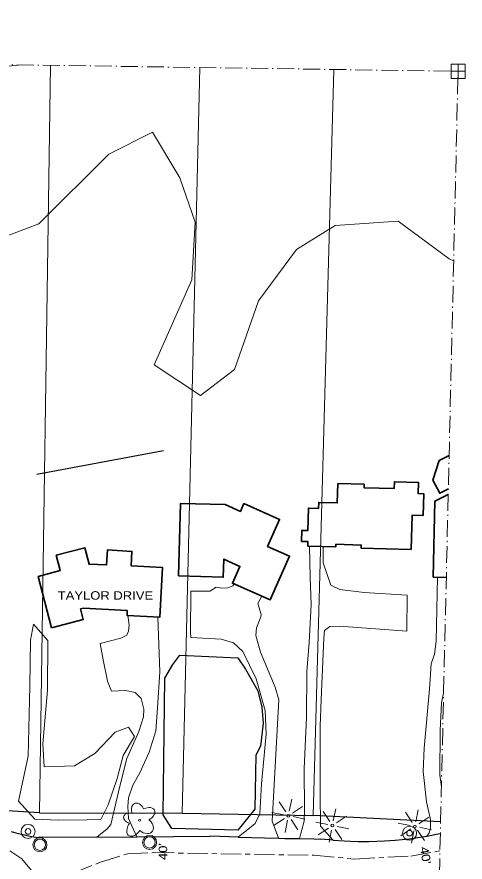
# Model space of a CAD drawing. Extents: x -861682 to -858969, y -1797841 to -1795153.
# Drawn here: x -859288 to -858969, y -1795757 to -1795158 of the extents above; entities that cross this region are included whole.
import ezdxf

# ---------------------------------------------------------------- set-up
doc = ezdxf.new("R2010")
doc.units = 0
doc.header["$LTSCALE"] = 2.4
doc.linetypes.add('DOT_DASHED', pattern=[7.7, 5, -1.2, 0.3, -1.2])
doc.linetypes.add('LONG_DASH_SHORT_DASH', pattern=[9.9, 6, -1.2, 1.5, -1.2])
for name, color, linetype, lineweight in [('10', 7, 'Continuous', 25), ('11', 7, 'Continuous', 13), ('12', 7, 'Continuous', 35), ('14', 7, 'Continuous', 25), ('17', 7, 'Continuous', 13), ('18', 7, 'Continuous', 13), ('30', 7, 'Continuous', 13), ('31', 7, 'Continuous', 13), ('32', 7, 'LONG_DASH_SHORT_DASH', 13), ('36', 7, 'Continuous', 13), ('42', 7, 'Continuous', 25), ('46', 7, 'Continuous', 13), ('61', 7, 'Continuous', 13)]:
    doc.layers.add(name, color=color, linetype=linetype, lineweight=lineweight)
doc.layers.add('43', color=7, linetype='Continuous')

msp = doc.modelspace()

# ---------------------------------------------------------------- linework, layer by layer
at = {"layer": '10'}
for p, q in [((-859230.781, -1795739.45), (-859272.109, -1795739.71)), ((-859130.522, -1795739.561), (-859150.348, -1795738.944)), ((-859062.976, -1795741.728), (-859071.75, -1795740.863))]:
    msp.add_line(p, q, dxfattribs=at)
for points in [[(-859291.594, -1795735.461), (-859288.291, -1795736.524), (-859277.069, -1795739.077), (-859272.109, -1795739.71)], [(-859230.781, -1795739.45), (-859202.511, -1795739.272), (-859150.348, -1795738.944)], [(-859130.522, -1795739.561), (-859111.795, -1795740.062), (-859101.943, -1795740.288)], [(-859101.943, -1795740.288), (-859097.473, -1795740.391), (-859086.862, -1795740.591)], [(-859086.862, -1795740.591), (-859076.749, -1795740.783), (-859071.75, -1795740.863)], [(-859062.976, -1795741.728), (-859055.28, -1795742.244), (-859050.876, -1795742.439), (-859045.368, -1795742.579), (-859043.164, -1795742.603), (-859040.96, -1795742.609), (-859037.654, -1795742.583), (-859032.146, -1795742.448), (-859026.642, -1795742.199), (-859018.947, -1795741.658), (-859009.083, -1795740.634), (-858998.176, -1795739.064), (-858996.617, -1795738.776)], [(-858996.617, -1795738.776), (-858988.463, -1795737.272), (-858987.024, -1795736.964)]]:
    msp.add_lwpolyline(points, dxfattribs=at)
at = {"layer": '11'}
for points in [[(-859079.865, -1795533.007), (-859079.451, -1795555.209), (-859078.572, -1795574.443), (-859080.099, -1795601.413), (-859081.687, -1795622.019), (-859082.041, -1795654.325), (-859083.692, -1795690.95), (-859083.301, -1795720.031), (-859083.759, -1795728.122), (-859086.862, -1795740.591)], [(-859070.103, -1795533.269), (-859070.088, -1795544.987), (-859064.66, -1795560.825), (-859058.323, -1795563.713), (-859041.158, -1795565.88), (-859010.659, -1795567.747), (-859010.846, -1795593.387), (-859058.541, -1795589.913), (-859065.539, -1795590.009), (-859069.327, -1795592.992), (-859069.732, -1795598.275), (-859071.632, -1795641.773), (-859072.292, -1795660.886), (-859072.28, -1795708.462), (-859071.978, -1795731.67), (-859062.976, -1795741.728)], [(-858989.081, -1795555.168), (-858989.922, -1795600.415), (-858991.154, -1795609.763), (-858993.574, -1795616.512), (-858994.731, -1795634.472), (-858998.44, -1795676.392), (-858999.092, -1795692.87), (-858996.795, -1795714.364), (-858994.07, -1795727.062), (-858993.989, -1795733.075), (-858994.954, -1795736.464), (-858996.617, -1795738.776)], [(-859133.293, -1795559.908), (-859134.27, -1795561.133), (-859137.867, -1795562.616), (-859142.409, -1795562.781), (-859146.059, -1795562.082), (-859150.585, -1795565.058), (-859164.004, -1795565.001), (-859164.381, -1795594.004), (-859164.035, -1795597.818), (-859142.455, -1795598.969), (-859133.711, -1795601.538), (-859127.175, -1795607.74), (-859117.627, -1795627.15), (-859111.239, -1795649.613), (-859110.644, -1795666.407), (-859113.912, -1795701.781), (-859115.187, -1795723.073), (-859118.522, -1795729.841), (-859130.522, -1795739.561)], [(-859113.738, -1795568.59), (-859116.608, -1795573.764), (-859114.269, -1795581.486), (-859114.364, -1795583.167), (-859117.552, -1795591.068), (-859117.924, -1795596.388), (-859114.657, -1795608.203), (-859104.327, -1795633.033), (-859101.534, -1795642.046), (-859106.338, -1795728.141), (-859101.943, -1795740.288)], [(-859208.745, -1795582.207), (-859207.806, -1795588.945), (-859208.266, -1795593.346), (-859209.619, -1795596.151), (-859213.681, -1795598.381), (-859228.443, -1795602.183), (-859226.423, -1795613.682), (-859223.211, -1795628.938), (-859220.375, -1795635.95), (-859210.435, -1795635.388), (-859203.629, -1795636.828), (-859199.44, -1795641.035), (-859197.446, -1795648.633), (-859197.722, -1795654.134), (-859201.059, -1795664.662), (-859209.517, -1795683.719), (-859214.562, -1795703.321), (-859220.95, -1795730.507), (-859223.44, -1795733.529), (-859230.781, -1795739.45)], [(-859187.392, -1795583.462), (-859186.147, -1795622.216), (-859187.665, -1795647.781), (-859189.009, -1795664.079), (-859193.773, -1795679.34), (-859200.259, -1795693.976), (-859205.252, -1795702.724), (-859208.215, -1795711.622), (-859208.846, -1795717.805), (-859208.348, -1795726.372), (-859202.511, -1795739.272)], [(-858984.702, -1795637.258), (-858986.213, -1795644.126), (-858987.117, -1795663.822), (-858987.434, -1795695.498), (-858986.252, -1795703.832)]]:
    msp.add_lwpolyline(points, dxfattribs=at)
at = {"layer": '12'}
msp.add_line((-858982.794, -1795555.319), (-858992.181, -1795555.094), dxfattribs=at)
for points in [[(-858981.327, -1795492.318), (-858987.472, -1795495.486), (-858992.217, -1795486.281), (-858987.848, -1795472.344), (-858980.777, -1795468.699)], [(-858992.181, -1795555.094), (-858990.883, -1795501.126), (-858981.421, -1795496.385)]]:
    msp.add_lwpolyline(points, dxfattribs=at)
for points in [[(-859007.647, -1795535.345), (-859043.222, -1795534.385), (-859043.164, -1795532.24), (-859061.136, -1795531.754), (-859061.183, -1795533.508), (-859081.111, -1795532.974), (-859081.028, -1795529.861), (-859085.542, -1795529.741), (-859085.333, -1795521.863), (-859081.052, -1795521.977), (-859080.628, -1795506.045), (-859073.408, -1795506.237), (-859073.296, -1795502.043), (-859060.114, -1795502.395), (-859059.748, -1795488.682), (-859041.117, -1795489.179), (-859041.182, -1795491.625), (-859019.778, -1795492.194), (-859019.65, -1795487.384), (-859002.594, -1795487.838), (-859002.803, -1795495.703), (-858998.779, -1795495.81), (-858999.191, -1795511.298), (-859007.002, -1795511.09)], [(-859172.795, -1795554.211), (-859171.355, -1795502.711), (-859139.606, -1795503.599), (-859128.918, -1795508.345), (-859126.468, -1795502.827), (-859101.107, -1795514.087), (-859109.591, -1795533.196), (-859094.042, -1795540.099), (-859107.851, -1795571.204), (-859134.518, -1795559.364), (-859129.214, -1795547.418), (-859140.687, -1795542.232), (-859141.047, -1795555.099)], [(-859263.001, -1795590.988), (-859272.459, -1795554.471), (-859256.757, -1795550.404), (-859259.592, -1795539.458), (-859239.305, -1795534.204), (-859236.281, -1795545.88), (-859223.885, -1795546.363), (-859223.261, -1795535.753), (-859205.939, -1795536.771), (-859206.538, -1795546.96), (-859184.118, -1795548.278), (-859186.204, -1795583.532), (-859209.382, -1795582.17), (-859209.183, -1795578.785), (-859240.312, -1795577.058), (-859242.426, -1795577.606), (-859240.471, -1795585.154)]]:
    msp.add_lwpolyline(points, close=True, dxfattribs=at)
at = {"layer": '14'}
msp.add_line((-859273.428, -1795481.906), (-859183.436, -1795465.071), dxfattribs=at)
for points in [[(-859182.593, -1795626.694), (-859176.951, -1795617.035), (-859172.007, -1795610.392), (-859130.65, -1795612.242), (-859125.27, -1795620.242), (-859116.619, -1795635.63), (-859113.696, -1795647.32), (-859112.691, -1795658.726)], [(-859112.691, -1795658.726), (-859114.555, -1795674.941), (-859117.944, -1795681.426), (-859118.708, -1795719.752), (-859130.656, -1795734.677), (-859177.459, -1795733.433), (-859183.731, -1795723.801), (-859182.593, -1795626.694)]]:
    msp.add_lwpolyline(points, dxfattribs=at)
at = {"layer": '17'}
for p, q in [((-859096.658, -1795721.504), (-859101.448, -1795714.376)), ((-859094.198, -1795721.044), (-859092.472, -1795712.644)), ((-859098.158, -1795723.704), (-859106.62, -1795722.03)), ((-859091.998, -1795722.444), (-859084.902, -1795717.704)), ((-859065.425, -1795728.402), (-859070.215, -1795721.274)), ((-859062.965, -1795727.942), (-859061.239, -1795719.542)), ((-859006.922, -1795729.044), (-859011.712, -1795721.916)), ((-859004.462, -1795728.584), (-859002.736, -1795720.184)), ((-859097.618, -1795726.204), (-859104.844, -1795731.06)), ((-859097.238, -1795736.164), (-859095.558, -1795727.564)), ((-859092.898, -1795727.104), (-859088.098, -1795734.318)), ((-859091.558, -1795724.964), (-859083.078, -1795726.688)), ((-859066.925, -1795730.602), (-859075.387, -1795728.928)), ((-859060.765, -1795729.342), (-859053.669, -1795724.602)), ((-859008.422, -1795731.244), (-859016.884, -1795729.57)), ((-859002.262, -1795729.984), (-858995.166, -1795725.244)), ((-859066.385, -1795733.102), (-859073.611, -1795737.958)), ((-859066.005, -1795743.062), (-859064.325, -1795734.462)), ((-859061.665, -1795734.002), (-859056.865, -1795741.216)), ((-859060.325, -1795731.862), (-859051.845, -1795733.586)), ((-859007.882, -1795733.744), (-859015.108, -1795738.6)), ((-859007.502, -1795743.704), (-859005.822, -1795735.104)), ((-859003.162, -1795734.644), (-858998.362, -1795741.858)), ((-859001.822, -1795732.504), (-858993.342, -1795734.228))]:
    msp.add_line(p, q, dxfattribs=at)
msp.add_lwpolyline([(-859200.252, -1795734.881), (-859199.21, -1795735.649), (-859197.804, -1795736.371), (-859196.556, -1795736.777), (-859195.184, -1795736.973), (-859194.166, -1795736.923), (-859193.022, -1795736.633), (-859192.09, -1795736.081), (-859191.35, -1795735.293), (-859190.882, -1795734.335), (-859190.672, -1795733.257), (-859190.776, -1795732.061), (-859191.066, -1795730.889), (-859191.552, -1795729.829), (-859192.274, -1795728.685), (-859193.14, -1795727.765), (-859193.822, -1795727.153), (-859192.64, -1795726.437), (-859191.494, -1795725.489), (-859190.574, -1795724.397), (-859190.052, -1795723.541), (-859189.72, -1795722.727), (-859189.574, -1795721.911), (-859189.614, -1795721.149), (-859189.83, -1795720.469), (-859190.088, -1795720.017), (-859190.508, -1795719.543), (-859190.968, -1795719.189), (-859191.534, -1795718.899), (-859192.77, -1795718.571), (-859194.012, -1795718.537), (-859196.058, -1795718.913), (-859197.718, -1795719.551), (-859198.508, -1795717.973), (-859199.162, -1795717.159), (-859199.574, -1795716.757), (-859200.038, -1795716.357), (-859200.64, -1795715.965), (-859201.644, -1795715.533), (-859202.658, -1795715.363), (-859203.546, -1795715.463), (-859204.346, -1795715.797), (-859205.012, -1795716.283), (-859205.572, -1795716.989), (-859205.922, -1795717.745), (-859206.08, -1795718.183), (-859206.248, -1795718.859), (-859206.3, -1795720.021), (-859206.228, -1795720.919), (-859206.016, -1795721.881), (-859205.732, -1795722.687), (-859207.174, -1795722.455), (-859208.532, -1795722.505), (-859209.69, -1795722.791), (-859210.578, -1795723.289), (-859211.018, -1795723.633), (-859211.452, -1795724.199), (-859211.69, -1795724.733), (-859211.814, -1795725.411), (-859211.612, -1795726.515), (-859211.156, -1795727.327), (-859210.532, -1795728.089), (-859209.754, -1795728.705), (-859209.056, -1795729.129), (-859208.392, -1795729.417), (-859207.664, -1795729.655), (-859208.348, -1795730.867), (-859208.97, -1795732.235), (-859209.366, -1795733.737), (-859209.5, -1795735.071), (-859209.49, -1795736.161), (-859209.156, -1795737.179), (-859208.634, -1795738.025), (-859208.076, -1795738.461), (-859207.69, -1795738.707), (-859206.956, -1795738.931), (-859206.162, -1795738.943), (-859205.392, -1795738.819), (-859204.732, -1795738.607), (-859203.988, -1795738.285), (-859202.912, -1795737.605), (-859201.95, -1795736.819), (-859200.994, -1795735.801), (-859200.248, -1795734.891)], dxfattribs=at)
for centre, radius in [((-859094.858, -1795724.404), 1), ((-859200.432, -1795727.469), 0.773), ((-859063.625, -1795731.302), 1), ((-859005.122, -1795731.944), 1)]:
    msp.add_circle(centre, radius, dxfattribs=at)
at = {"layer": '18'}
for points in [[(-860031.965, -1795256.805), (-860007.111, -1795284.53), (-859998.226, -1795306.326), (-859971.824, -1795305.466), (-859954.869, -1795276.595), (-859940.292, -1795258.059), (-859894.343, -1795245.833), (-859819.814, -1795239.581), (-859736.012, -1795233.398), (-859631.487, -1795229.196), (-859534.524, -1795216.449), (-859460.922, -1795207.967), (-859360.864, -1795199.506), (-859284.202, -1795191.583), (-859284.171, -1795191.579)], [(-858977.563, -1795330.702), (-858980.643, -1795329.274), (-859016.932, -1795302.448), (-859061.655, -1795305.432), (-859089.121, -1795322.606), (-859116.091, -1795358.957), (-859133.112, -1795407.607), (-859157.144, -1795426.205), (-859190.062, -1795404.383), (-859163.458, -1795344.083), (-859161.006, -1795303.251), (-859171.907, -1795271.748), (-859191.221, -1795239.277), (-859222.39, -1795254.835), (-859272.03, -1795304.309), (-859307.248, -1795317.53), (-859343.21, -1795340.793), (-859407.446, -1795360.101), (-859462.61, -1795408.489), (-859467.136, -1795437.538), (-859522.644, -1795429.933), (-859590.119, -1795425.164)]]:
    msp.add_lwpolyline(points, dxfattribs=at)
msp.add_lwpolyline([(-859222.668, -1795716.512), (-859228.036, -1795726.925), (-859237.932, -1795727.314), (-859258.178, -1795727.432), (-859274.799, -1795726.843), (-859286.475, -1795713.989), (-859279.461, -1795681.954), (-859278.342, -1795632.404), (-859277.893, -1795599.646), (-859275.64, -1795588.389), (-859265.615, -1795599.99), (-859265.78, -1795635.188), (-859269.059, -1795673.232), (-859268.26, -1795689.546), (-859246.646, -1795688.837), (-859232.235, -1795680.06), (-859217.852, -1795664.957), (-859208.239, -1795661.496), (-859204.15, -1795668.087), (-859212.193, -1795681.687), (-859216.341, -1795697.861)], close=True, dxfattribs=at)
at = {"layer": '30'}
for p, q in [((-859271.551, -1795722.255), (-859263.639, -1795191.879)), ((-859157.815, -1795193.425), (-859170.33, -1795722.47)), ((-859062.523, -1795194.818), (-859077.159, -1795724.261))]:
    msp.add_line(p, q, dxfattribs=at)
at = {"layer": '31'}
for centre, radius in [((-859279.624, -1795735.505), 5), ((-859279.624, -1795735.505), 2), ((-859008.853, -1795736.71), 5), ((-859008.853, -1795736.71), 2)]:
    msp.add_circle(centre, radius, dxfattribs=at)
at = {"layer": '32'}
for points in [[(-859608.727, -1795645.905), (-859547.475, -1795663.972), (-859512.218, -1795672.548), (-859448.852, -1795685.888), (-859390.25, -1795702.087), (-859346.418, -1795718.286), (-859312.114, -1795735.914), (-859284.005, -1795754.971), (-859271.617, -1795770.217), (-859251.13, -1795810.238), (-859242.554, -1795833.584), (-859228.738, -1795871.699), (-859218.732, -1795901.238), (-859209.68, -1795935.065), (-859202.057, -1795970.321), (-859196.34, -1796004.625), (-859192.528, -1796042.264), (-859177.759, -1796158.991), (-859172.04, -1796220.929), (-859156.019, -1796407.84)], [(-859269.621, -1795774.116), (-859228.136, -1795757.194), (-859208.945, -1795751.33), (-859190.274, -1795750.512), (-859076.743, -1795752.396), (-859047.957, -1795755.062), (-859007.977, -1795752.929), (-858987.309, -1795749.224)]]:
    msp.add_lwpolyline(points, dxfattribs=at)
at = {"layer": '36'}
for centre, radius in [((-859271.235, -1795744.924), 5), ((-859271.235, -1795744.924), 4), ((-859193.349, -1795743.29), 5), ((-859193.349, -1795743.29), 4)]:
    msp.add_circle(centre, radius, dxfattribs=at)
at = {"layer": '42'}
for p, q in [((-859271.551, -1795722.255), (-859294.243, -1795720.911)), ((-859271.551, -1795722.255), (-859170.33, -1795722.47)), ((-859170.33, -1795722.47), (-859077.159, -1795724.261)), ((-858986.83, -1795728.651), (-859077.159, -1795724.261))]:
    msp.add_line(p, q, dxfattribs=at)
at = {"layer": '61', "linetype": 'DOT_DASHED'}
for p in [(-861615.801, -1795157.51), (-859035.9, -1797835.881)]:
    msp.add_line(p, (-858974.429, -1795196.105), dxfattribs=at)
at = {"layer": '61'}
for p, q in [((-858979.429, -1795191.105), (-858969.429, -1795191.105)), ((-858979.429, -1795201.105), (-858979.429, -1795191.105)), ((-858974.429, -1795191.105), (-858974.429, -1795196.105)), ((-858969.429, -1795201.105), (-858969.429, -1795191.105)), ((-858969.429, -1795196.105), (-858979.429, -1795196.105)), ((-858979.429, -1795201.105), (-858969.429, -1795201.105)), ((-858974.429, -1795201.105), (-858974.429, -1795196.105))]:
    msp.add_line(p, q, dxfattribs=at)

# ---------------------------------------------------------------- texts
at = {"layer": '43'}
for rotation, width, p in [(90, 1.15, (-859180.866, -1795755.782)), (280.081, 1.2, (-859001.58, -1795746.798))]:
    msp.add_text("40'", height=6, rotation=rotation, dxfattribs=dict(at, width=width)).set_placement(p)
at = {"layer": '46', "width": 1.15}
msp.add_text('TAYLOR DRIVE', height=6, dxfattribs=at).set_placement((-859258.524, -1795571.04))

doc.saveas('drawing.dxf')
